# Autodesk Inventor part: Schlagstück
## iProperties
Created: 2005-12
Part Number: Schlagstück
Document SubType Name: Modeling
Designer: Kumpf
Manufacturer: Standard
Standards Organization: Custom
Material: PA
Author: Kumpf
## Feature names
1. Drehung1 [Revolution]
2. Bohrung1 [Hole]
